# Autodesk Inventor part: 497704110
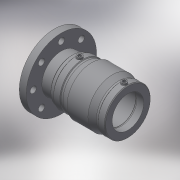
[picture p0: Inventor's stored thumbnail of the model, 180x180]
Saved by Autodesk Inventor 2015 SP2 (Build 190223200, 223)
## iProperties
Created: 2017-06
Part Number: 497704110
Material: Generic
Description: PLASSON PE CAST IRON SPIGOT COUPLER TRANSITION 225-200
Document SubType Name: Modeling
Designer: KIM
Mass: 55.0731 g
Surface Area: 148.067 cm^2
Volume: 55.0731 cm^3
Density: 1 g/cm^3
Appearance: Default
Author: KIM
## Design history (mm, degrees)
derived "497704.ipt"
feature "Solid1::497704.ipt"
tag "TaggingFeature1"
body "Solid1"
other parameters: "d13" = 162, "d14" = 17.6296, "d17" = 104.5, "d19" = 3.52592, "d20" = 168 deg, "d22" = 149.46, "d23" = 159, "d24" = 144.9762, "d25" = 135 deg, "d26" = 64.8, "d27" = 135 deg, "d29" = 79, "d35" = 15, "d39" = 5 deg, "d45" = 4, "d46" = 14, "d47" = 0, "d50" = 3, "d51" = 0, "d52" = 23.2, "d53" = 5.8, "d55" = 0.1, "d56" = 141.51, "d58" = 61, "d60" = 84, "d62" = 4.77, "d65" = 3.18, "d68" = 159, "d70" = 22, "d71" = 7.33333, "d72" = 127.359, "d73" = 13.2, "d74" = 18, "d77" = 0, "d79" = 360 deg, "L_" = 223, "D_1" = 159, "A_" = 79, "d_2" = 12, "L_2" = 61, "H_" = 109, "d_1" = 84, "t_" = 22, "S_" = 18
